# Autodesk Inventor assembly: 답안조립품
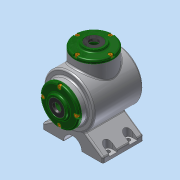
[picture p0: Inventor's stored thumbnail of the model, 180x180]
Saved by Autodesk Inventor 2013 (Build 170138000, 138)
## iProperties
Created: 2017-04
Part Number: 답안조립품
Document SubType Name: Assembly
Designer: dgall
Author: dgall
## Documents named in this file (5)
- C:\Users\dgall\Desktop\470407V1004\답안조립품.iam
- C:\Users\dgall\Desktop\470407V1004\본체.ipt
- C:\Users\dgall\Desktop\470407V1004\커버.ipt
- C:\Users\dgall\Desktop\470407V1004\볼트 M4.ipt
- C:\Users\dgall\Desktop\470407V1004\오일실 17 32 8.ipt
